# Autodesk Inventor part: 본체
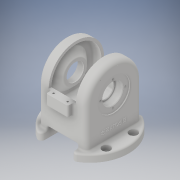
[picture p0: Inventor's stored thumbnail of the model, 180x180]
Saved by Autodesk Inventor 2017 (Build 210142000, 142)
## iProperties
Part Number: 본체
Material: 일반
Document SubType Name: Modeling
Designer: MRC
Density: 1 g/cm^3
Appearance: 기본값
Author: MRC
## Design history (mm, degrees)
sketch "스케치1"
  geometry: C1 r 71 at (0, 0); 1 further point
  constraints: 1 centre point, 1 coincident
  dimensions: "d0" = 142 diameter of C1
extrude "돌출1" new body sketch "스케치1" distance "d1" = 13; taper "d2" = 0 deg
sketch "스케치2"
  geometry: L1 (-44, 51)-(44, 51); L2 (44, 51)-(44, -51); L3 (44, -51)-(-44, -51); L4 (-44, -51)-(-44, 51); L5 (-44, 51)-(44, -51); L6 (44, 51)-(-44, -51); 1 further point
  constraints: 12 end point, 2 midpoint, 2 parallel, 1 horizontal, 1 perpendicular
  dimensions: "d3" = 88 distance of L2.end L3.end; "d4" = 102 distance of L1.end L2.end
extrude "돌출2" join sketch "스케치2" distance "d5" = 68; taper "d6" = 0 deg
sketch "스케치3"
  geometry: L1 (81, -51)-(81, 51) reference; C1 r 51 at (81, 0); 1 further point
  constraints: 1 centre point, 1 midpoint
  dimensions: "d7" = 102 diameter of C1
extrude "돌출3" join sketch "스케치3" stored distance "d8" = 88; taper "d9" = 0 deg
sketch "스케치5"
  geometry: L1 (71, 13)-(-71, 13) reference; L2 (-71, 0)-(71, 0) reference; L3 (-28, 19)-(28, 19); L4 (28, 19)-(28, 0); L5 (28, 0)-(-28, 0); L6 (-28, 0)-(-28, 19); 2 further points
  constraints: 8 end point, 2 midpoint, 2 parallel, 1 horizontal, 1 perpendicular, 1 point on line
  dimensions: "d10" = 56 distance of L3.start L3.end; "d11" = 19 distance of L3.end L4.end
extrude "돌출4" cut sketch "스케치5" stored distance "d12" = 142; taper "d13" = 0 deg
sketch "스케치6"
  geometry: L1 (28, -51)-(-28, -51) reference; L2 (28, -51)-(28, 51) reference; L3 (-28, 51)-(28, 51) reference; L4 (-28, 51)-(-28, -51) reference; C1 r 14 at (0, 0); 1 further point
  constraints: 1 centre point, 1 coincident
  dimensions: "d15" = 28 diameter of C1
extrude "돌출5" cut sketch "스케치6" distance "d16" = 37; taper "d17" = 0 deg
sketch "스케치7"
  geometry: C1 r 30 at (0, 0); 1 further point
  constraints: 1 centre point, 1 coincident
  dimensions: "d18" = 60 diameter of C1
extrude "돌출6" cut sketch "스케치7" distance "d19" = 22; taper "d20" = 0 deg
sketch "스케치8"
  geometry: L1 (16, -62)-(16, -68) reference; L2 (0, -68)-(16, -68) reference; L3 (0, -68)-(0, 0) reference; L4 (88, 0)-(0, 0) reference; L5 (88, -68)-(88, 0) reference; L6 (72, -68)-(88, -68) reference; L7 (72, -68)-(72, -62) reference; L8 (72, -62)-(16, -62) reference; L9 (24, 0)-(64, 0); L10 (64, 0)-(64, -20); L11 (64, -20)-(24, -20); L12 (24, -20)-(24, 0); 2 further points
  constraints: 8 end point, 2 midpoint, 2 parallel, 1 horizontal, 1 perpendicular, 1 point on line
  dimensions: "d21" = 40 distance of L10.end L11.end; "d22" = 20 distance of L9.end L10.end
extrude "돌출7" join sketch "스케치8" distance "d23" = 10; taper "d24" = 0 deg
sketch "스케치10"
  geometry: L1 (-39, 81)-(39, 81); L2 (39, 81)-(39, 40); L3 (39, 40)-(-39, 40); L4 (-39, 40)-(-39, 81); L5 (-44, 13)-(-44, 81) reference; L6 (44, 13)-(44, 81) reference; 2 further points
  constraints: 8 end point, 2 parallel, 1 horizontal, 1 horizontal alignment, 1 midpoint, 1 perpendicular
  dimensions: "d25" = 40 distance from line of point (0, 0) L3; "d26" = 5 distance between parallel lines of L5 L4; "d27" = 5 distance between parallel lines of L6 L2
extrude "돌출8" cut sketch "스케치10" stored distance "d28" = 92; taper "d29" = 0 deg
sketch "스케치11"
  geometry: L1 (-44, 81)-(-20, 81) reference; L2 (-20, 81)-(20, 81) reference; L3 (20, 81)-(44, 81) reference; L4 (44, 81)-(44, 81) reference; L5 (44, 81)-(20, 81) reference; L6 (20, 81)-(-20, 81) reference; L7 (-20, 81)-(-44, 81) reference; L8 (-44, 81)-(-44, 81) reference; L9 (-25, 132)-(25, 132); L10 (25, 132)-(25, 81); L11 (25, 81)-(-25, 81); L12 (-25, 81)-(-25, 132); 2 further points
  constraints: 8 end point, 2 midpoint, 2 parallel, 1 horizontal, 1 perpendicular, 1 point on line
  dimensions: "d30" = 50 distance of L9.start L9.end; "d31" = 51 distance of L9.end L10.end
extrude "돌출9" cut sketch "스케치11" stored distance "d32" = 102; taper "d33" = 0 deg
sketch "스케치13"
  geometry: L1 (46, 0)-(-46, 0) reference; L2 (-46, 0)-(46, 0); A1 r 51 centre (0, 0) between (51, 0) and (-51, 0) reference; A2 r 46 centre (0, 0) between (46, 0) and (-46, 0); 1 further point
  constraints: 2 end point, 2 point on circle, 1 centre point, 1 coincident, 1 collinear
extrude "돌출11" cut sketch "스케치13" distance "d40" = 14; taper "d41" = 0 deg
sketch "스케치15"
  geometry: L1 (-25, 81)-(25, 81) reference; L2 (25, 81)-(39, 81) reference; L3 (-39, 81)-(-55.824, 81); L4 (39, 81)-(50.959, 81); L5 (44, 81)-(25, 81) reference; L6 (-39, 127)-(-39, 81) reference; L7 (-39, 81)-(-39, 114.5); L8 (-39, 114.5)-(-27, 102.5); L9 (-39, 81)-(-27, 81); L10 (-27, 102.5)-(-27, 81); L11 (-39, 81)-(-25, 81) reference; 1 further point
  constraints: 12 end point, 2 point on line, 1 collinear, 1 horizontal, 1 perpendicular
  dimensions: "d42" = 67 diameter of L7.end L9; "d43" = 135 deg angle of L8 L6; "d44" = 12 distance between parallel lines of L6 L10
revolve "회전1" sketch "스케치15" stored, may be unused: angle "d45" = 90 deg
sketch "스케치16"
  geometry: C1 r 30 at (51, 68); A1 r 51 centre (51, 68) between (102, 68) and (0, 68) reference; 1 further point
  constraints: 1 centre point, 1 coincident
  dimensions: "d46" = 60 diameter of C1
extrude "돌출12" cut sketch "스케치16" distance "d47" = 2; taper "d48" = 0 deg
sketch "스케치17"
  geometry: C1 r 30 at (0, 0) reference; C2 r 18.5 at (0, 0); 1 further point
  constraints: 1 centre point, 1 coincident
  dimensions: "d49" = 37 diameter of C2
extrude "돌출13" cut sketch "스케치17" distance "d50" = 13; taper "d51" = 0 deg
sketch "스케치18"
  geometry: C1 r 21.5 at (0, 0) reference; C2 r 16 at (0, 0); 1 further point
  constraints: 1 centre point, 1 coincident
  dimensions: "d52" = 32 diameter of C2
extrude "돌출14" cut sketch "스케치18" stored distance "d53" = 32 (= d52); taper "d54" = 0 deg
sketch "스케치19"
  geometry: C1 r 14 at (0, 0) reference; C2 r 11 at (0, 0); 1 further point
  constraints: 1 centre point, 1 coincident
  dimensions: "d55" = 22 diameter of C2
extrude "돌출15" cut sketch "스케치19" stored distance "d56" = 13; taper "d57" = 0 deg
sketch "스케치20"
  geometry: L1 (-28, -10.77)-(-28, -65.246) reference; L2 (-28, 65.246)-(-28, 10.77) reference; L3 (28, 10.77)-(28, 65.246) reference; L4 (28, -65.246)-(28, -10.77) reference; L5 (-55, -25)-(55, -25); L6 (55, -25)-(55, 25); L7 (55, 25)-(-55, 25); L8 (-55, 25)-(-55, -25); L9 (-55, -25)-(55, 25); L10 (55, -25)-(-55, 25); A1 r 30 centre (0, 0) between (-28, 10.77) and (-28, -10.77) reference; A2 r 71 centre (0, 0) between (-28, 65.246) and (-28, -65.246) reference; A3 r 30 centre (0, 0) between (28, -10.77) and (28, 10.77) reference; A4 r 71 centre (0, 0) between (28, -65.246) and (28, 65.246) reference; 5 further points
  constraints: 12 end point, 4 coincident, 2 midpoint, 2 parallel, 1 horizontal, 1 perpendicular
  dimensions: "d58" = 110 distance of L7.end L6.end; "d59" = 50 distance of L6.end L5.end
hole "구멍1" sketch "스케치20" at (-55, 25), (-55, -25), (55, -25), (55, 25) diameter "d60" = 9; stored, may be unused: countersink angle "d64" = 90 deg, drill point angle "d66" = 118 deg; dims "d61" = 6, "d62" = 15, "d63" = 8.8, "d65" = 13
sketch "스케치21" dims "d67" = 46
  geometry: C1 r 14 at (0, 0) reference; 3 further points
  constraints: 2 vertical alignment, 1 coincident, 2 other
hole "구멍2" sketch "스케치21" at (0, 23) diameter "d68" = 3.242; stored, may be unused: countersink angle "d72" = 90 deg, drill point angle "d74" = 118 deg; dims "d69" = 8, "d70" = 15, "d71" = 8.8, "d73" = 10
sketch "스케치22" dims "d78" = 46
  geometry: C1 r 30 at (0, 0) reference; 3 further points
  constraints: 2 vertical alignment, 1 coincident, 2 other
hole "구멍3" sketch "스케치22" at (0, 23) diameter "d79" = 3.242; stored, may be unused: countersink angle "d83" = 90 deg, drill point angle "d85" = 118 deg; dims "d80" = 8, "d81" = 15, "d82" = 8.8, "d84" = 10
sketch "스케치23"
  geometry: L1 (7, 7)-(33, 7); L2 (33, 7)-(33, 115); L3 (33, 115)-(7, 115); L4 (7, 115)-(7, 7); L5 (7, 7)-(33, 115); L6 (33, 7)-(7, 115); 5 further points
  constraints: 12 end point, 4 coincident, 2 midpoint, 2 parallel, 1 horizontal, 1 perpendicular
  dimensions: "d89" = 26 distance of L3.end L2.end; "d90" = 108 distance of L2.end L1.end
hole "구멍4" sketch "스케치23" at (7, 115), (33, 115), (33, 7), (7, 7) diameter "d91" = 3.242; stored, may be unused: countersink angle "d95" = 90 deg, drill point angle "d97" = 118 deg; dims "d92" = 8, "d93" = 15, "d94" = 8.8, "d96" = 10
fillet "모깎기1" dims "d98" = 0.3
fillet "모깎기2" dims "d99" = 8
fillet "모깎기3" dims "d100" = 6
fillet "모깎기4" dims "d101" = 3
fillet "모깎기5" dims "d102" = 3
fillet "모깎기6" dims "d103" = 3
fillet "모깎기7" dims "d104" = 3
fillet "모깎기8" dims "d105" = 3
chamfer "모따기1" distance "d106" = 1; stored, may be unused: second distance "d107" = 2, angle "d108" = 45 deg
fillet "모깎기9" dims "d109" = 3
fillet "모깎기10" dims "d110" = 3
fillet "모깎기11" dims "d111" = 3
fillet "모깎기12" dims "d112" = 3
sketch "스케치24"
  geometry: L1 (-60.512, -81)-(60.512, -81) reference; 3 further points
  constraints: 1 midpoint, 1 vertical alignment, 1 other
  dimensions: "d113" = 30 distance from line of L1 point (0, -51)
feature "엠보싱1" sketch "스케치24" dims "d114" = 0.5, "d115" = 0
node "솔리드1"
mirror "미러1"
mirror "미러2"
mirror "미러3"
mirror "미러4"
pattern_circular "원형 패턴1" dims angle "d76" = 360 deg
pattern_circular "원형 패턴2" dims angle "d87" = 360 deg
mirror "미러5"
node "투영된 루프1"
node "투영된 루프2"
node "투영된 루프3"
node "투영된 루프4"
node "투영된 루프6"
node "투영된 루프7"
node "투영된 루프8"
node "투영된 루프9"
node "투영된 루프10"
